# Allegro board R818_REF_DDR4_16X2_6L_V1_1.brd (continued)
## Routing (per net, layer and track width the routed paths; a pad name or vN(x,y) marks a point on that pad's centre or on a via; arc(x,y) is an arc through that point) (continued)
SDQM3: length 21.3
  TOP w0.102: v1(18.3,27.47) 18.29,27.46 U1.U11 ; v1(17.55,13.52) 18.67,13.52 UD2.E7
  SIG04 w0.114: v1(17.55,13.52) 17.55,12.7 17.04,12.19 16.51,12.19 16.45,12.25 16.44,12.25 15.76,12.94 15.76,13.13 15.01,13.88 15.01,14.87 14.72,15.15 14.72,16.46 14.66,16.53 14.66,20.53 16.84,22.72 16.84,23.49 17.9,24.55 17.9,27.06 v1(18.3,27.47)
SDQS0N: length 20.5
  TOP w0.076: 13.03,26.21 13.39,26.21 13.64,25.96 U1.Y3
  TOP w0.097: UD1.F3 4.92,12.48 5.08,12.48 5.12,12.48 5.83,13.2 5.83,13.33 v1(5.8,13.37) ; 13.03,26.21 12.88,26.21 12.86,26.19 10.48,26.19 10.05,25.76 10.05,25.45 9.94,25.34 v1(9.91,25.34)
  SIG04 w0.097: v1(5.8,13.37) 5.8,13.6 6.17,13.97 6.17,15.56 5.42,16.31 5.42,19.05 6.68,20.31 6.68,21.41 9.91,24.64 v1(9.91,25.34)
SDQS0P: length 20.1
  TOP w0.097: v1(6.37,13.37) 6.37,13.37 6.25,13.37 6.15,13.27 6.15,13.06 5.25,12.16 5.07,12.16 4.97,12.16 UD1.G3 ; v1(10.45,25.34) 10.36,25.42 10.36,25.63 10.61,25.87 13.07,25.87 13.15,25.96 U1.Y2
  SIG04 w0.097: v1(10.45,25.34) 10.23,25.12 10.23,24.51 6.99,21.27 6.99,20.17 5.74,18.92 5.74,16.44 6.49,15.7 6.49,13.84 6.29,13.64 6.29,13.5 6.37,13.42 v1(6.37,13.37)
SDQS1N: length 18.4
  TOP w0.076: U1.AC2 13.29,24.32 12.32,23.36 12.32,23.28
  TOP w0.097: 12.32,23.28 12.16,23.12 11.5,23.12 10.02,21.64 10.02,21.46 10.23,21.25 10.23,21.1 10.02,20.89 10.02,20.57 9.41,19.96 8.95,19.96 8.63,20.29 8.49,20.29 8.23,20.02 8.23,19.79 8.75,19.26 8.75,18.6 8.26,18.11 7.14,18.11 6.74,17.71 6.74,17.31 7.07,16.97 7.07,16.45 6.64,16.01 6.64,14.91 6.74,14.82 7.01,14.82 7.17,14.97 7.17,15.65 7.27,15.75 7.27,15.95 7.36,16.05 7.56,16.05 7.76,16.25 7.99,16.25 8.1,16.36 8.1,16.6 8.01,16.7 UD1.A7
SDQS1P: length 18.5
  TOP w0.076: 12.1,23.51 12.22,23.51 13.04,24.32 13.04,24.57 13.29,24.82 U1.AB2
  TOP w0.097: 12.1,23.51 12.03,23.44 11.37,23.44 9.71,21.77 9.71,20.7 9.28,20.28 9.08,20.28 8.76,20.6 8.36,20.6 7.91,20.15 7.91,19.66 8.41,19.15 8.41,18.71 8.13,18.43 7.01,18.43 6.42,17.84 6.42,17.18 6.76,16.84 6.76,16.58 6.32,16.15 6.32,14.78 6.61,14.5 7.14,14.5 7.48,14.84 7.48,15.52 7.86,15.9 UD1.B7
SDQS2N: length 12.3
  TOP w0.076: 15.91,23.64 15.91,23.86 15.71,24.06 15.71,24.33 15.79,24.4 U1.AC7
  TOP w0.097: 15.91,23.64 15.91,22 14.75,20.83 14.75,19.73 16.93,17.55 16.93,17.06 17.02,16.97 17.02,16.83 16.93,16.74 16.93,16.56 17.27,16.21 17.44,16.21 17.54,16.31 17.68,16.31 17.78,16.21 17.96,16.21 18.1,16.35 18.23,16.35 18.37,16.21 18.52,16.21 18.55,16.25 18.8,16.25 18.81,16.26 18.91,16.36 18.91,16.6 18.81,16.7 UD2.A7
SDQS2P: length 12.4
  TOP w0.076: 15.6,23.69 15.6,23.93 15.54,23.99 15.54,24.56 15.65,24.67 15.69,24.71 15.69,24.86 U1.AB7
  TOP w0.097: 15.6,23.69 15.6,22.13 14.43,20.96 14.43,19.6 16.61,17.42 16.61,16.42 17.14,15.9 UD2.B7
SDQS3N: length 15.4
  TOP w0.076: U1.AA10 17.29,25.31 17.04,25.06 17.04,24.85 17.03,24.85 17.03,24.24 17.1,24.17 17.1,24.04 17.19,23.95 17.19,23.89
  TOP w0.097: UD2.F3 15.71,12.48 15.9,12.48 16.29,12.88 16.29,13.08 16.46,13.25 v1(16.83,13.25) ; v1(17.34,21.5) 17.19,21.65 17.19,23.89
  SIG04 w0.097: v1(17.34,21.5) 17.13,21.5 15.88,20.25 15.88,16.64 16.77,15.75 16.77,13.32 16.83,13.26 v1(16.83,13.25)
SDQS3P: length 15.6
  TOP w0.076: U1.AB10 17.21,24.89 17.21,24.78 17.21,24.78 17.21,24.31 17.28,24.24 17.28,24.11 17.5,23.89
  TOP w0.097: v1(17.59,21.99) 17.5,22.08 17.5,23.89 ; v1(16.68,12.66) 16.52,12.66 16.03,12.17 15.69,12.17 15.5,11.98 15.5,11.9 UD2.G3
  SIG04 w0.097: v1(16.68,12.66) 16.45,12.88 16.45,15.62 15.56,16.51 15.56,20.38 17.04,21.86 17.46,21.86 v1(17.59,21.99)
SODT0: length 49.1
  TOP w0.076: 21.65,23.17 21.65,23.24 20.68,24.21 20.54,24.35 20.54,24.59 20.79,24.84 U1.AB17
  TOP w0.102: UD2.K3 15.84,9.5 17.14,10.8 v1(17.14,10.97) 17.41,10.7 17.41,8.27 18.19,7.49 19.67,7.49 19.91,7.25 19.91,6.95 20.21,6.65 20.51,6.65 21.25,5.92 23.67,5.92 26.06,8.31 26.06,15.08 25.73,15.41 25.73,19.58 24.76,20.54 24.02,20.54 22.79,21.77 22.31,21.77 21.67,22.41 21.67,23.15 21.65,23.17 ; v1(5.21,9.5) UD1.K3
  SIG04 w0.114: v1(17.14,10.97) 16.26,10.97 16.09,11.14 14.81,11.14 14.55,11.4 9.56,11.4 9.27,11.11 8.12,11.11 6.88,9.86 5.57,9.86 v1(5.21,9.5)
SRAS: length 41.7
  TOP w0.102: UD2.L8 19.9,9.1 20.73,9.1 20.83,9.2 v1(20.83,9.21) 20.91,9.21 21.34,8.79 21.48,8.79 21.89,9.2 21.89,9.34 21.61,9.62 21.61,9.78 21.73,9.9 21.9,9.9 22.07,9.73 22.25,9.73 22.37,9.85 22.37,10.01 21.91,10.47 21.91,10.65 22.03,10.76 22.19,10.76 22.65,10.3 22.82,10.3 22.94,10.42 22.94,10.59 22.63,10.9 22.63,11.05 22.75,11.17 22.93,11.17 23.23,10.88 23.4,10.88 24.64,12.12 24.64,14.49 23.83,15.3 23.83,15.44 23.93,15.54 24.03,15.54 24.14,15.64 24.14,15.85 24.04,15.95 23.76,15.95 23.55,15.73 23.4,15.73 23.03,16.11 23.03,16.25 23.13,16.35 23.99,16.35 24.14,16.5 24.14,16.84 23.94,17.03 23.68,17.03 23.55,17.16 23.37,17.16 23.28,17.25 23.28,17.46 23.42,17.6 23.91,17.6 23.99,17.68 23.99,17.96 23.89,18.06 23.63,18.06 23.5,18.19 23.5,18.33 23.79,18.62 23.79,18.87 22.26,20.4 22.05,20.4 20.75,21.7 20.75,23.23 19.9,24.08 19.9,24.34 U1.AC15 ; v1(10.89,9.45) 10.51,9.08 9.09,9.08 UD1.L8
  SIG04 w0.114: v1(20.83,9.21) 20.77,9.21 20.26,8.7 18.47,8.7 17.92,9.24 15.49,9.24 15.28,9.46 14.38,9.46 14.38,9.46 10.9,9.46 v1(10.89,9.45)
SRST: length 59.5
  TOP w0.102: UD2.P1 14.3,5.89 14.3,3.62 14.68,3.24 14.68,1.8 14.82,1.66 v1(14.82,1.19) ; v1(3.5,4.31) 3.5,5.9 UD1.P1 ; U1.U17 21.28,26.97 v1(21.31,26.97)
  SIG04 w0.114: 14.83,1.19 v1(14.82,1.19) ; 14.83,1.19 8.98,1.19 6.87,3.3 5.18,3.3 4.17,4.31 v1(3.5,4.31) ; 14.83,1.19 15.78,1.19 16.75,2.16 22.49,2.16 22.87,2.54 23.67,2.54 27.43,6.3 27.43,20.11 26,21.54 26,22.14 25.26,22.88 25.26,23.05 23.18,25.12 22.38,25.12 21.93,25.58 21.93,26.51 21.47,26.97 v1(21.31,26.97)
STEN1: length 5.9
  TOP w0.102: RD1.1 11,2.94 11,5.76 11.1,5.86 11.1,6.79 10.79,7.1 UD1.N9
STEN2: length 3
  TOP w0.102: UD2.N9 20.48,6.91 21.69,6.91 22.03,7.25 RD2.1
SVREF: length 27.4
  TOP w0.356: RD8.1 6.24,0.26 11.43,0.26 12.1,0.92 12.1,2.2 CD34.1 12.24,2.86 12.24,6.24 UD2.M1
  TOP w0.4: RD7.2 CD33.1 5.04,1.06 5.05,1.05 RD8.1 ; 0.49,4.7 CD35.1 0.92,5.26 1.86,6.2 1.86,6.65 UD1.M1
  TOP w0.406: 0.49,4.7 0.49,2.56 1.98,1.06 RD7.2
SWE: length 41.1
  TOP w0.076: U1.AA12 18.04,25.21 18.04,24.85 18.23,24.66 18.23,24.2 18.23,24.2 18.37,24.06 18.37,23.9
  TOP w0.102: v1(19.07,20.18) 18.69,20.18 18.44,20.43 18.44,20.95 18.73,21.24 18.73,22.08 18.61,22.2 18.61,22.48 18.37,22.73 18.37,23.9 ; UD1.L2 v1(4.3,8.3) ; UD2.L2 v1(15.1,9.1)
  SIG04 w0.114: v1(4.3,8.3) 4.3,8.41 4.98,9.08 5.45,9.08 6.25,8.28 7.77,8.28 8.17,8.68 8.6,8.68 8.69,8.77 9.37,8.77 9.67,9.07 12.72,9.07 13.09,8.7 14.4,8.7 14.8,9.1 v1(15.1,9.1) 15.27,8.93 17.75,8.93 18.34,8.33 20.97,8.33 20.98,8.34 20.99,8.34 21.33,8.68 21.33,9.64 21.71,10.02 21.71,10.43 21.7,10.44 21.7,10.45 21.49,10.66 21.48,10.66 21.37,10.77 21.37,11.2 22.03,11.87 22.03,17.09 21.04,18.08 21.04,18.61 21.39,18.96 21.39,19.27 21.24,19.42 21.24,20.02 20.93,20.32 19.21,20.32 v1(19.07,20.18)
N16281101: length 2.4
  TOP w0.102: v1(22.34,25.93) 22.32,25.96 U1.Y19
  BOTTOM w0.254: v1(22.34,25.93) 22.45,25.83 23.45,25.83 RD5.1
N17928021: length 11.5
  TOP w0.102: RD3.1 1.84,9.45 v1(1.87,9.48) ; UD1.F9 v1(10.01,12.7)
  SIG04 w0.114: v1(1.87,9.48) 2.31,9.92 4.16,9.92 5.16,10.92 6.89,10.92 7.88,11.9 8.42,11.9 8.67,12.15 8.67,12.37 8.99,12.7 v1(10.01,12.7)
N17931224: length 2.8
  TOP w0.102: UD2.F9 22.85,12.7 RD4.1

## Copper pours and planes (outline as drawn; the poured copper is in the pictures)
GND on GND02, GND03, GND05: 0.14,36.1 0.14,0.12 27.55,0.12 27.55,36.1
VCC25-DRAM on TOP: 23.42,4.21 23.87,4.21 24.49,3.59 25.56,3.59 25.72,3.43 25.72,2.89 25.13,2.3 24.55,2.3 23.23,3.61 23.23,4.08 23.36,4.21 23.42,4.21
VCC25-DRAM on SIG04: 25.79,2.51 25.79,3.39 25.66,3.53 25.41,3.53 24.26,2.38 24.26,1.74 25.03,1.74
VCC-DRAM on BOTTOM: 0.14,17.37 0.16,17.39 0.16,19.35 8.03,27.22 15.21,27.22 16.21,28.22 16.21,28.56 16.48,28.83 17.37,28.83 17.67,28.53 17.67,28.52 17.77,28.43 18.69,28.43 18.7,28.44 20.51,28.44 20.51,28.43 21.18,27.76 21.21,27.76 22.09,26.88 22.09,26.58 27.55,21.12 27.55,0.12 0.14,0.12

Small or netless copper shapes (teardrops, artwork), in the pictures only: 4 on TOP
